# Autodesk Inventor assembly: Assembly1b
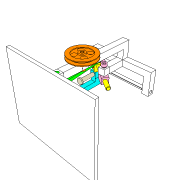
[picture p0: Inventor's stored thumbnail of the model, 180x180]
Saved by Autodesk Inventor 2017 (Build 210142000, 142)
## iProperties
Created: 2015-03
Part Number: Assembly1b
Document SubType Name: Assembly
Designer: Administrator
Author: Administrator
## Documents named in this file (12)
- F:\YouTube\2020\YouTube\11N\15PickPlace\Assembly1.iam
- F:\YouTube\2020\YouTube\11N\15PickPlace\Runway.ipt
- F:\YouTube\2020\YouTube\11N\15PickPlace\Crank1a.ipt
- F:\YouTube\2020\YouTube\11N\15PickPlace\BearingB.ipt
- F:\YouTube\2020\YouTube\11N\15PickPlace\Crank1.ipt
- F:\YouTube\2020\YouTube\11N\15PickPlace\Pin.ipt
- F:\YouTube\2020\YouTube\11N\15PickPlace\Slider1.ipt
- F:\YouTube\2020\YouTube\11N\15PickPlace\Slider2.ipt
- F:\YouTube\2020\YouTube\11N\15PickPlace\Slider3.ipt
- F:\YouTube\2020\YouTube\11N\15PickPlace\Crank0.ipt
- F:\YouTube\2020\YouTube\11N\15PickPlace\Rocker.ipt
- F:\YouTube\2020\YouTube\11N\15PickPlace\Slider4.ipt
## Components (16 placed, 11 different names)
1. Runway:1 — Mate:23, Mate:24, Mate:34, Angle:3
2. BearingB:2 — Flush:1, Flush:2, Mate:41, Mate:42, Mate:43, Flush:3, Flush:4, Flush:5
3. BearingB:3 — Flush:3, Flush:4, Flush:5, Mate:45, Flush:6
4. BearingB:1 — Mate:21, Mate:22, Mate:23, Mate:24, Angle:2, Flush:1, Flush:2, Mate:41
5. Crank1a:1 — Mate:21, Mate:22, Insert:1, Mate:30, Mate:31, Mate:32, Mate:33
6. Crank1:1 — Insert:1, Angle:2, Mate:30, Insert:2
7. Pin:1 — Mate:31, Mate:32
8. Pin:2 — Mate:35, Mate:36
9. Slider1:1 — Mate:33, Mate:38
10. Slider2:1 — Mate:34, Mate:35, Mate:36, Mate:37
11. Slider3:1 — Mate:37, Angle:3, Mate:38, Mate:39, Mate:40
12. Pin:3 — Mate:39, Mate:40
13. Crank0:1 — Mate:42, Mate:43, Insert:3
14. Rocker:1 — Mate:45, Mate:46, Mate:47, Flush:6
15. Slider4:1 — Insert:3, Mate:47
16. Slider4:2 — Insert:2, Mate:46
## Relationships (32: Mate 21, Flush 6, Insert 3, Angle 2)
- Mate:21: BearingB:1 ↔ Crank1a:1
- Mate:22: BearingB:1 ↔ Crank1a:1
- Mate:23: Runway:1 ↔ BearingB:1
- Mate:24: Runway:1 ↔ BearingB:1
- Insert:1: Crank1a:1 ↔ Crank1:1
- Angle:2: BearingB:1 ↔ Crank1:1
- Flush:1: BearingB:2 ↔ BearingB:1
- Flush:2: BearingB:2 ↔ BearingB:1
- Mate:30: Crank1a:1 ↔ Crank1:1
- Mate:31: Crank1a:1 ↔ Pin:1
- Mate:32: Crank1a:1 ↔ Pin:1
- Mate:33: Crank1a:1 ↔ Slider1:1
- Mate:34: Runway:1 ↔ Slider2:1
- Mate:35: Pin:2 ↔ Slider2:1
- Mate:36: Pin:2 ↔ Slider2:1
- Mate:37: Slider2:1 ↔ Slider3:1
- Angle:3: Runway:1 ↔ Slider3:1
- Mate:38: Slider1:1 ↔ Slider3:1
- Mate:39: Slider3:1 ↔ Pin:3
- Mate:40: Slider3:1 ↔ Pin:3
- Mate:41: BearingB:2 ↔ BearingB:1
- Mate:42: BearingB:2 ↔ Crank0:1
- Mate:43: BearingB:2 ↔ Crank0:1
- Flush:3: BearingB:2 ↔ BearingB:3
- Flush:4: BearingB:2 ↔ BearingB:3
- Flush:5: BearingB:2 ↔ BearingB:3
- Mate:45: BearingB:3 ↔ Rocker:1
- Insert:2: Crank1:1 ↔ Slider4:2
- Mate:46: Rocker:1 ↔ Slider4:2
- Insert:3: Crank0:1 ↔ Slider4:1
- Mate:47: Rocker:1 ↔ Slider4:1
- Flush:6: BearingB:3 ↔ Rocker:1
